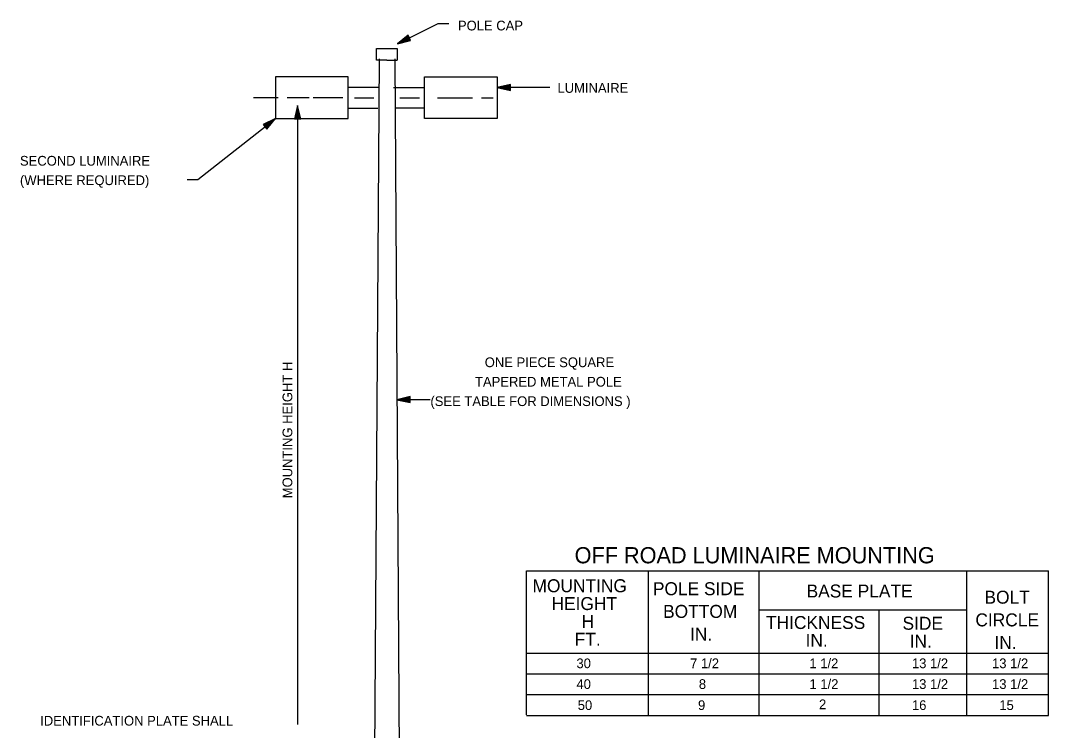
# Model space of a CAD drawing. Extents: x 9989.4 to 10000.1, y 10000.3 to 10010.3.
# Drawn here: x 9989.7 to 9996.04, y 10005.94 to 10010.31 of the extents above; entities that cross this region are included whole.
import ezdxf

# ---------------------------------------------------------------- set-up
doc = ezdxf.new("R2010")
doc.units = 0
for name, color, linetype in [('DETL-DIMS', 7, 'Continuous'), ('DETL-LINE', 7, 'Continuous'), ('DETL-NOTE', 7, 'Continuous')]:
    doc.layers.add(name, color=color, linetype=linetype)

msp = doc.modelspace()

# ---------------------------------------------------------------- linework, layer by layer
at = {"layer": 'DETL-DIMS'}
for p, q in [((9992.968, 10009.9005), (9992.644, 10009.9005)), ((9991.412, 10009.79), (9991.412, 10005.9723)), ((9992.23, 10007.975), (9992.026, 10007.975))]:
    msp.add_line(p, q, dxfattribs=at)
for points in [[(9992.029, 10010.17), (9992.281, 10010.295), (9992.346, 10010.295)], [(9992.094, 10010.224), (9992.029, 10010.17), (9992.11, 10010.19), (9992.094, 10010.224)], [(9992.093, 10010.221), (9992.036, 10010.174), (9992.108, 10010.192), (9992.093, 10010.221)], [(9992.093, 10010.218), (9992.043, 10010.177), (9992.105, 10010.193), (9992.093, 10010.218)], [(9992.092, 10010.216), (9992.05, 10010.181), (9992.103, 10010.194), (9992.092, 10010.216)], [(9992.091, 10010.213), (9992.057, 10010.184), (9992.1, 10010.195), (9992.091, 10010.213)], [(9992.091, 10010.21), (9992.064, 10010.188), (9992.098, 10010.196), (9992.091, 10010.21)], [(9992.09, 10010.207), (9992.071, 10010.191), (9992.095, 10010.197), (9992.09, 10010.207)], [(9992.09, 10010.204), (9992.078, 10010.195), (9992.093, 10010.198), (9992.09, 10010.204)], [(9992.089, 10010.202), (9992.085, 10010.199), (9992.09, 10010.2), (9992.089, 10010.202)], [(9992.726, 10009.9205), (9992.644, 10009.9005), (9992.726, 10009.8825), (9992.726, 10009.9205)], [(9992.724, 10009.9175), (9992.652, 10009.9005), (9992.724, 10009.8845), (9992.724, 10009.9175)], [(9992.722, 10009.9155), (9992.66, 10009.9005), (9992.722, 10009.8865), (9992.722, 10009.9155)], [(9992.721, 10009.9135), (9992.668, 10009.9005), (9992.721, 10009.8895), (9992.721, 10009.9135)], [(9992.719, 10009.9115), (9992.676, 10009.9005), (9992.719, 10009.8915), (9992.719, 10009.9115)], [(9992.717, 10009.9085), (9992.684, 10009.9005), (9992.717, 10009.8935), (9992.717, 10009.9085)], [(9992.715, 10009.9065), (9992.691, 10009.9005), (9992.715, 10009.8955), (9992.715, 10009.9065)], [(9992.714, 10009.9045), (9992.699, 10009.9015), (9992.714, 10009.8975), (9992.714, 10009.9045)], [(9992.712, 10009.9025), (9992.707, 10009.9015), (9992.712, 10009.9005), (9992.712, 10009.9025)], [(9991.432, 10009.708), (9991.412, 10009.79), (9991.394, 10009.708), (9991.432, 10009.708)], [(9991.429, 10009.71), (9991.412, 10009.782), (9991.396, 10009.71), (9991.429, 10009.71)], [(9991.427, 10009.712), (9991.412, 10009.774), (9991.398, 10009.712), (9991.427, 10009.712)], [(9991.425, 10009.713), (9991.412, 10009.766), (9991.401, 10009.713), (9991.425, 10009.713)], [(9991.423, 10009.715), (9991.412, 10009.758), (9991.403, 10009.715), (9991.423, 10009.715)], [(9990.732, 10009.334), (9990.797, 10009.334), (9991.276, 10009.71)], [(9991.224, 10009.644), (9991.276, 10009.71), (9991.201, 10009.673), (9991.224, 10009.644)], [(9991.224, 10009.647), (9991.27, 10009.705), (9991.203, 10009.673), (9991.224, 10009.647)], [(9991.224, 10009.65), (9991.264, 10009.7), (9991.206, 10009.672), (9991.224, 10009.65)], [(9991.224, 10009.652), (9991.257, 10009.695), (9991.209, 10009.671), (9991.224, 10009.652)], [(9991.42, 10009.717), (9991.412, 10009.75), (9991.405, 10009.717), (9991.42, 10009.717)], [(9991.418, 10009.719), (9991.412, 10009.743), (9991.407, 10009.719), (9991.418, 10009.719)], [(9991.416, 10009.72), (9991.413, 10009.735), (9991.409, 10009.72), (9991.416, 10009.72)], [(9991.414, 10009.722), (9991.413, 10009.727), (9991.412, 10009.722), (9991.414, 10009.722)], [(9991.224, 10009.655), (9991.251, 10009.69), (9991.211, 10009.671), (9991.224, 10009.655)], [(9991.224, 10009.658), (9991.245, 10009.685), (9991.214, 10009.67), (9991.224, 10009.658)], [(9991.224, 10009.661), (9991.239, 10009.681), (9991.217, 10009.67), (9991.224, 10009.661)], [(9991.224, 10009.664), (9991.233, 10009.675), (9991.219, 10009.669), (9991.224, 10009.664)], [(9991.224, 10009.667), (9991.227, 10009.671), (9991.222, 10009.668), (9991.224, 10009.667)], [(9992.108, 10007.995), (9992.026, 10007.975), (9992.108, 10007.957), (9992.108, 10007.995)], [(9992.106, 10007.992), (9992.034, 10007.975), (9992.106, 10007.959), (9992.106, 10007.992)], [(9992.104, 10007.99), (9992.042, 10007.975), (9992.104, 10007.961), (9992.104, 10007.99)], [(9992.103, 10007.988), (9992.05, 10007.975), (9992.103, 10007.964), (9992.103, 10007.988)], [(9992.101, 10007.986), (9992.057, 10007.975), (9992.101, 10007.966), (9992.101, 10007.986)], [(9992.099, 10007.983), (9992.066, 10007.975), (9992.099, 10007.968), (9992.099, 10007.983)], [(9992.097, 10007.981), (9992.073, 10007.975), (9992.097, 10007.97), (9992.097, 10007.981)], [(9992.096, 10007.979), (9992.081, 10007.976), (9992.096, 10007.972), (9992.096, 10007.979)], [(9992.094, 10007.977), (9992.089, 10007.976), (9992.094, 10007.975), (9992.094, 10007.977)]]:
    msp.add_lwpolyline(points, dxfattribs=at)
at = {"layer": 'DETL-LINE'}
for p, q in [((9991.9, 10010.142), (9992.028, 10010.142)), ((9991.9, 10010.07), (9991.9, 10010.142)), ((9992.028, 10010.142), (9992.028, 10010.07)), ((9991.916, 10010.078), (9991.876, 10004.038)), ((9992.012, 10010.078), (9992.052, 10004.038)), ((9991.964, 10010.07), (9991.9, 10010.07)), ((9991.964, 10010.07), (9992.028, 10010.07)), ((9991.724, 10009.966), (9991.276, 10009.966)), ((9991.276, 10009.966), (9991.276, 10009.71)), ((9991.724, 10009.902), (9991.724, 10009.966)), ((9992.196, 10009.966), (9992.644, 10009.966)), ((9992.196, 10009.902), (9992.196, 10009.966)), ((9992.644, 10009.966), (9992.644, 10009.71)), ((9991.916, 10009.902), (9991.724, 10009.902)), ((9991.724, 10009.774), (9991.724, 10009.902)), ((9992.004, 10009.902), (9992.196, 10009.902)), ((9992.196, 10009.774), (9992.196, 10009.902)), ((9991.292, 10009.838), (9991.14, 10009.838)), ((9991.484, 10009.838), (9991.348, 10009.838)), ((9991.412, 10009.838), (9991.364, 10009.838)), ((9991.692, 10009.838), (9991.508, 10009.838)), ((9991.764, 10009.838), (9991.884, 10009.838)), ((9992.044, 10009.838), (9992.164, 10009.838)), ((9992.276, 10009.838), (9992.492, 10009.838)), ((9992.548, 10009.838), (9992.62, 10009.838)), ((9991.724, 10009.71), (9991.724, 10009.774)), ((9991.724, 10009.774), (9991.908, 10009.774)), ((9992.196, 10009.774), (9992.012, 10009.774)), ((9992.196, 10009.71), (9992.196, 10009.774)), ((9991.276, 10009.71), (9991.724, 10009.71)), ((9992.644, 10009.71), (9992.196, 10009.71))]:
    msp.add_line(p, q, dxfattribs=at)
at = {"layer": 'DETL-NOTE'}
for p, q in [((9992.8239, 10006.032), (9992.8239, 10006.92)), ((9992.8239, 10006.92), (9996.0449, 10006.92)), ((9993.5769, 10006.032), (9993.5769, 10006.92)), ((9994.2609, 10006.032), (9994.2609, 10006.92)), ((9995.5409, 10006.027), (9995.5409, 10006.92)), ((9996.0449, 10006.027), (9996.0449, 10006.92)), ((9994.2609, 10006.678), (9995.5409, 10006.678)), ((9995.0009, 10006.032), (9995.0009, 10006.678)), ((9992.8239, 10006.412), (9996.0449, 10006.412)), ((9992.8239, 10006.284), (9996.0449, 10006.284)), ((9992.8239, 10006.156), (9996.0449, 10006.156))]:
    msp.add_line(p, q, dxfattribs=at)
msp.add_lwpolyline([(9992.8239, 10006.027), (9996.0449, 10006.027)], dxfattribs=at)

# ---------------------------------------------------------------- texts
for s, height, p in [('POLE CAP', 0.06, (9992.402, 10010.253)), ('LUMINAIRE', 0.06, (9993.016, 10009.8683)), ('SECOND LUMINAIRE', 0.06, (9989.7, 10009.419)), ('(WHERE REQUIRED)', 0.06, (9989.7, 10009.299)), ('ONE PIECE SQUARE', 0.06, (9992.5674, 10008.176)), ('TAPERED METAL POLE', 0.06, (9992.5074, 10008.056)), ('(SEE TABLE FOR DIMENSIONS )', 0.06, (9992.2322, 10007.936)), ('OFF ROAD LUMINAIRE MOUNTING', 0.100002, (9993.1218, 10006.9658)), ('MOUNTING', 0.08, (9992.8621, 10006.7876)), ('POLE SIDE', 0.08, (9993.6048, 10006.7693)), ('BASE PLATE', 0.08, (9994.553, 10006.7551)), ('BOLT', 0.08, (9995.6503, 10006.717)), ('HEIGHT', 0.08, (9992.9793, 10006.6776)), ('BOTTOM', 0.08, (9993.6676, 10006.6293)), ('CIRCLE', 0.08, (9995.5942, 10006.577)), ('H', 0.08, (9993.1651, 10006.5676)), ('THICKNESS', 0.08, (9994.3024, 10006.5608)), ('SIDE', 0.08, (9995.1446, 10006.5562)), ('FT.', 0.08, (9993.1225, 10006.4576)), ('IN.', 0.08, (9993.8335, 10006.4893)), ('IN.', 0.08, (9994.5467, 10006.4508)), ('IN.', 0.08, (9995.1886, 10006.4462)), ('IN.', 0.08, (9995.7121, 10006.437)), ('30', 0.06, (9993.1331, 10006.319)), ('7 1/2', 0.06, (9993.8342, 10006.319)), ('1 1/2', 0.06, (9994.5702, 10006.319)), ('13 1/2', 0.06, (9995.2028, 10006.319)), ('13 1/2', 0.06, (9995.6969, 10006.319)), ('40', 0.06, (9993.1331, 10006.191)), ('8', 0.06, (9993.8882, 10006.191)), ('1 1/2', 0.06, (9994.5708, 10006.191)), ('13 1/2', 0.06, (9995.2028, 10006.191)), ('13 1/2', 0.06, (9995.6969, 10006.191)), ('50', 0.06, (9993.1411, 10006.061)), ('9', 0.06, (9993.8832, 10006.061)), ('2', 0.06, (9994.6294, 10006.066)), ('16', 0.06, (9995.2028, 10006.061)), ('15', 0.06, (9995.7418, 10006.061)), ('IDENTIFICATION PLATE SHALL ', 0.06, (9989.8248, 10005.965))]:
    msp.add_text(s, height=height, dxfattribs=at).set_placement(p)
msp.add_text('MOUNTING HEIGHT H', height=0.06, rotation=90, dxfattribs=at).set_placement((9991.38, 10007.3671))

doc.saveas('drawing.dxf')
